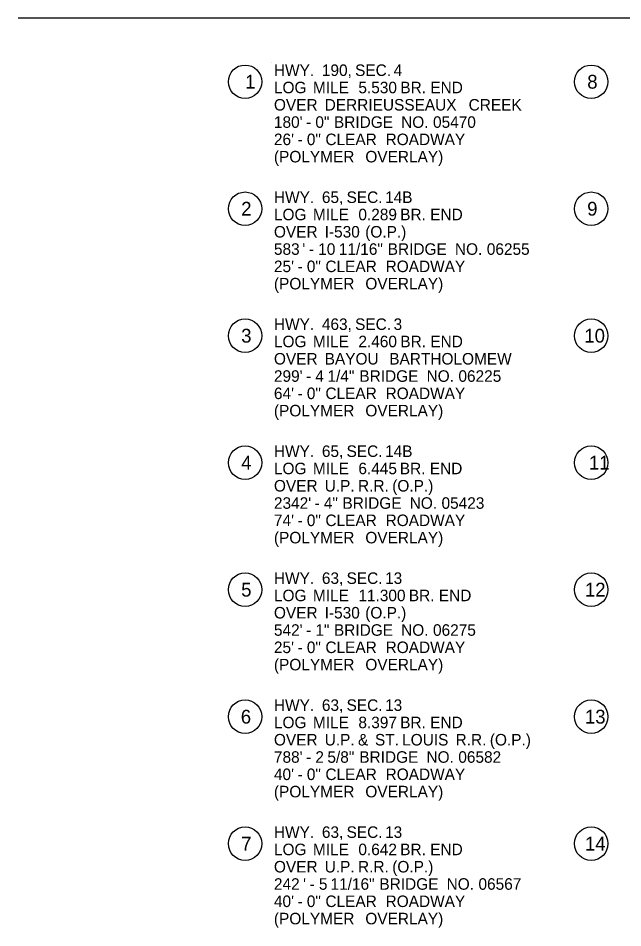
# Model space of a CAD drawing. Extents: x 1930546 to 1934225, y 596452 to 599536.
# Drawn here: x 1930546 to 1931071, y 598574 to 599364 of the extents above; entities that cross this region are included whole.
import ezdxf

# ---------------------------------------------------------------- set-up
doc = ezdxf.new("R2010")
doc.units = 0
doc.layers.add('Default', color=7, linetype='Continuous')
doc.layers.add('R_Border', color=7, linetype='Continuous')

msp = doc.modelspace()

# ---------------------------------------------------------------- linework, layer by layer
at = {"layer": 'R_Border'}
for p, q in [((1932141.6, 599363.54), (1930546.24, 599363.54)), ((1930766.22, 599325.41), (1930766.22, 599325.41))]:
    msp.add_line(p, q, dxfattribs=at)
for centre in [(1930743.17, 599308.41), (1931043.47, 599308.41), (1930743.17, 599198.23), (1931043.47, 599198.23), (1930743.17, 599088.06), (1931043.47, 599088.06), (1930743.17, 598977.88), (1931043.47, 598977.88), (1930743.17, 598867.71), (1931043.47, 598867.71), (1930743.17, 598757.53), (1931043.47, 598757.53), (1930743.17, 598647.36), (1931043.47, 598647.36)]:
    msp.add_circle(centre, 14.52, dxfattribs=at)

# ---------------------------------------------------------------- texts
at = {"layer": 'Default'}
for s, p in [('HWY.', (1930768.17, 599313.41)), (' 190,', (1930806.07, 599313.41)), (' SEC.', (1930834.87, 599313.41)), (' 4', (1930868.28, 599313.41)), ('LOG', (1930768.17, 599298.41)), (' MILE', (1930798.29, 599298.41)), (' 5.530', (1930837.74, 599298.41)), (' BR.', (1930874.14, 599298.41)), (' END', (1930900.17, 599298.41)), ('OVER', (1930768.17, 599283.41)), (' DERRIEUSSEAUX', (1930808.49, 599283.41)), (' CREEK', (1930933.41, 599283.41)), ("180'", (1930768.17, 599268.41)), (' 0"', (1930800.4, 599268.41)), (' BRIDGE', (1930816.53, 599268.41)), (' NO.', (1930874.84, 599268.41)), (' 05470', (1930902.5, 599268.41)), (' -', (1930792.37, 599268.41)), ("26'", (1930768.17, 599253.41)), (' 0"', (1930793.01, 599253.41)), (' CLEAR', (1930809.14, 599253.41)), (' ROADWAY', (1930861.36, 599253.41)), (' -', (1930784.98, 599253.41)), ('(POLYMER', (1930768.17, 599238.41)), (' OVERLAY)', (1930843.77, 599238.41)), ('HWY.', (1930768.17, 599203.23)), (' 65,', (1930806.07, 599203.23)), (' SEC.', (1930827.48, 599203.23)), (' 14B', (1930860.89, 599203.23)), ('LOG', (1930768.17, 599188.23)), (' MILE', (1930798.29, 599188.23)), (' 0.289', (1930837.74, 599188.23)), (' BR.', (1930874.04, 599188.23)), (' END', (1930900.07, 599188.23)), ('OVER', (1930768.17, 599173.23)), (' I-530', (1930808.49, 599173.23)), (' (O.P.)', (1930843.66, 599173.23)), ('583', (1930768.17, 599158.23)), (" '", (1930789.1, 599158.23)), (' 10', (1930802.86, 599158.23)), (' 11/16"', (1930820.79, 599158.23)), (' BRIDGE', (1930863.2, 599158.23)), (' NO.', (1930921.51, 599158.23)), (' 06255', (1930949.17, 599158.23)), (' -', (1930794.83, 599158.23)), ("25'", (1930768.17, 599143.23)), (' 0"', (1930793.01, 599143.23)), (' CLEAR', (1930809.14, 599143.23)), (' ROADWAY', (1930861.36, 599143.23)), (' -', (1930784.98, 599143.23)), ('(POLYMER', (1930768.17, 599128.23)), (' OVERLAY)', (1930843.77, 599128.23)), ('HWY.', (1930768.17, 599093.06)), (' 463,', (1930806.07, 599093.06)), (' SEC.', (1930834.87, 599093.06)), (' 3', (1930868.28, 599093.06)), ('LOG', (1930768.17, 599078.06)), (' MILE', (1930798.29, 599078.06)), (' 2.460', (1930837.74, 599078.06)), (' BR.', (1930874.14, 599078.06)), (' END', (1930900.17, 599078.06)), ('OVER', (1930768.17, 599063.06)), (' BAYOU', (1930808.49, 599063.06)), (' BARTHOLOMEW', (1930864.52, 599063.06)), ("299'", (1930768.17, 599048.06)), (' 4', (1930800.4, 599048.06)), (' 1/4"', (1930810.96, 599048.06)), (' BRIDGE', (1930838.59, 599048.06)), (' NO.', (1930896.91, 599048.06)), (' 06225', (1930924.56, 599048.06)), (' -', (1930792.37, 599048.06)), ("64'", (1930768.17, 599033.06)), (' 0"', (1930793.01, 599033.06)), (' CLEAR', (1930809.14, 599033.06)), (' ROADWAY', (1930861.36, 599033.06)), (' -', (1930784.98, 599033.06)), ('(POLYMER', (1930768.17, 599018.06)), (' OVERLAY)', (1930843.77, 599018.06)), ('HWY.', (1930768.17, 598982.88)), (' 65,', (1930806.07, 598982.88)), (' SEC.', (1930827.48, 598982.88)), (' 14B', (1930860.89, 598982.88)), ('LOG', (1930768.17, 598967.88)), (' MILE', (1930798.29, 598967.88)), (' 6.445', (1930837.74, 598967.88)), (' BR.', (1930873.69, 598967.88)), (' END', (1930899.72, 598967.88)), ('OVER', (1930768.17, 598952.88)), (' U.P.', (1930808.49, 598952.88)), (' R.R.', (1930837.39, 598952.88)), (' (O.P.)', (1930867.11, 598952.88)), ("2342'", (1930768.17, 598937.88)), (' 4"', (1930807.78, 598937.88)), (' BRIDGE', (1930823.92, 598937.88)), (' NO.', (1930882.23, 598937.88)), (' 05423', (1930909.89, 598937.88)), (' -', (1930799.76, 598937.88)), ("74'", (1930768.17, 598922.88)), (' 0"', (1930793.01, 598922.88)), (' CLEAR', (1930809.14, 598922.88)), (' ROADWAY', (1930861.36, 598922.88)), (' -', (1930784.98, 598922.88)), ('(POLYMER', (1930768.17, 598907.88)), (' OVERLAY)', (1930843.77, 598907.88)), ('HWY.', (1930768.17, 598872.71)), (' 63,', (1930806.07, 598872.71)), (' SEC.', (1930827.48, 598872.71)), (' 13', (1930860.89, 598872.71)), ('LOG', (1930768.17, 598857.71)), (' MILE', (1930798.29, 598857.71)), (' 11.300', (1930837.74, 598857.71)), (' BR.', (1930881.53, 598857.71)), (' END', (1930907.56, 598857.71)), ('OVER', (1930768.17, 598842.71)), (' I-530', (1930808.49, 598842.71)), (' (O.P.)', (1930843.66, 598842.71)), ("542'", (1930768.17, 598827.71)), (' 1"', (1930800.4, 598827.71)), (' BRIDGE', (1930816.53, 598827.71)), (' NO.', (1930874.84, 598827.71)), (' 06275', (1930902.5, 598827.71)), (' -', (1930792.37, 598827.71)), ("25'", (1930768.17, 598812.71)), (' 0"', (1930793.01, 598812.71)), (' CLEAR', (1930809.14, 598812.71)), (' ROADWAY', (1930861.36, 598812.71)), (' -', (1930784.98, 598812.71)), ('(POLYMER', (1930768.17, 598797.71)), (' OVERLAY)', (1930843.77, 598797.71)), ('HWY.', (1930768.17, 598762.53)), (' 63,', (1930806.07, 598762.53)), (' SEC.', (1930827.48, 598762.53)), (' 13', (1930860.89, 598762.53)), ('LOG', (1930768.17, 598747.53)), (' MILE', (1930798.29, 598747.53)), (' 8.397', (1930837.74, 598747.53)), (' BR.', (1930874.01, 598747.53)), (' END', (1930900.04, 598747.53)), ('OVER', (1930768.17, 598732.53)), (' U.P.', (1930808.49, 598732.53)), (' &', (1930837.39, 598732.53)), (' ST.', (1930852.13, 598732.53)), (' LOUIS', (1930875.69, 598732.53)), (' R.R.', (1930922.08, 598732.53)), (' (O.P.)', (1930951.8, 598732.53)), ("788'", (1930768.17, 598717.53)), (' 2', (1930800.4, 598717.53)), (' 5/8"', (1930810.86, 598717.53)), (' BRIDGE', (1930838.49, 598717.53)), (' NO.', (1930896.8, 598717.53)), (' 06582', (1930924.46, 598717.53)), (' -', (1930792.37, 598717.53)), ("40'", (1930768.17, 598702.53)), (' 0"', (1930793.01, 598702.53)), (' CLEAR', (1930809.14, 598702.53)), (' ROADWAY', (1930861.36, 598702.53)), (' -', (1930784.98, 598702.53)), ('(POLYMER', (1930768.17, 598687.53)), (' OVERLAY)', (1930843.77, 598687.53)), ('HWY.', (1930768.17, 598652.36)), (' 63,', (1930806.07, 598652.36)), (' SEC.', (1930827.48, 598652.36)), (' 13', (1930860.89, 598652.36)), ('LOG', (1930768.17, 598637.36)), (' MILE', (1930798.29, 598637.36)), (' 0.642', (1930837.74, 598637.36)), (' BR.', (1930874.05, 598637.36)), (' END', (1930900.08, 598637.36)), ('OVER', (1930768.17, 598622.36)), (' U.P.', (1930808.49, 598622.36)), (' R.R.', (1930837.39, 598622.36)), (' (O.P.)', (1930867.11, 598622.36)), ('242', (1930768.17, 598607.36)), (" '", (1930789.72, 598607.36)), (' 5', (1930803.47, 598607.36)), (' 11/16"', (1930813.57, 598607.36)), (' BRIDGE', (1930855.98, 598607.36)), (' NO.', (1930914.29, 598607.36)), (' 06567', (1930941.95, 598607.36)), (' -', (1930795.44, 598607.36)), ("40'", (1930768.17, 598592.36)), (' -', (1930784.98, 598592.36)), (' 0"', (1930793.01, 598592.36)), (' CLEAR', (1930809.14, 598592.36)), (' ROADWAY', (1930861.36, 598592.36)), ('(POLYMER', (1930768.17, 598577.36)), (' OVERLAY)', (1930843.77, 598577.36))]:
    msp.add_text(s, height=10, rotation=360, dxfattribs=at).set_placement(p)
at = {"layer": 'R_Border'}
for s, p in [('1', (1930743.17, 599302.41)), ('8', (1931040.07, 599302.41)), ('2', (1930739.77, 599192.23)), ('9', (1931040.02, 599192.23)), ('3', (1930739.77, 599082.06)), ('10', (1931037.56, 599082.06)), ('4', (1930739.77, 598971.88)), ('11', (1931041.48, 598971.88)), ('5', (1930739.77, 598861.71)), ('12', (1931038.08, 598861.71)), ('6', (1930739.43, 598751.53)), ('13', (1931038.08, 598751.53)), ('7', (1930739.77, 598641.36)), ('14', (1931038.08, 598641.36))]:
    msp.add_text(s, height=12, rotation=360, dxfattribs=at).set_placement(p)

doc.saveas('drawing.dxf')
